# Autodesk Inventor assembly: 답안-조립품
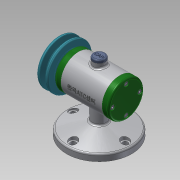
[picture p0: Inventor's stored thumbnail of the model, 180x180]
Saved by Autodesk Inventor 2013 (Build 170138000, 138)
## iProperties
Created: 2018-12
Part Number: 답안-조립품
Document SubType Name: Assembly
Designer: Administrator
Author: Administrator
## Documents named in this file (15)
- C:\Users\Administrator\Desktop\481207v1048\답안-조립품.iam
- C:\Users\Administrator\Desktop\481207v1048\답안도면.ipt
- C:\Users\Administrator\Desktop\481207v1048\V벨트풀리.ipt
- C:\Users\Administrator\Desktop\481207v1048\고무캡.ipt
- C:\Users\Administrator\Desktop\481207v1048\너트 M8.ipt
- 너트 M8.ipt
- C:\Users\Administrator\Desktop\481207v1048\뒤커버.ipt
- C:\Users\Administrator\Desktop\481207v1048\베어링 15 x 32 x 9.ipt
- C:\Users\Administrator\Desktop\481207v1048\볼트 M4 x 12.ipt
- C:\Users\Administrator\Desktop\481207v1048\스프링와셔 8.ipt
- C:\Users\Administrator\Desktop\481207v1048\앞커버.ipt
- C:\Users\Administrator\Desktop\481207v1048\오일 실 15 25 7.ipt
- C:\Users\Administrator\Desktop\481207v1048\와셔 8x17.ipt
- C:\Users\Administrator\Desktop\481207v1048\축.ipt
- C:\Users\Administrator\Desktop\481207v1048\키 3 x 3 x 12.ipt
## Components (2 placed, 2 different names)
1. V벨트풀리:1
2. 고무캡:1 — 플러쉬:2
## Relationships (1: Flush 1)
- 플러쉬:2 [Flush]: 고무캡:1
